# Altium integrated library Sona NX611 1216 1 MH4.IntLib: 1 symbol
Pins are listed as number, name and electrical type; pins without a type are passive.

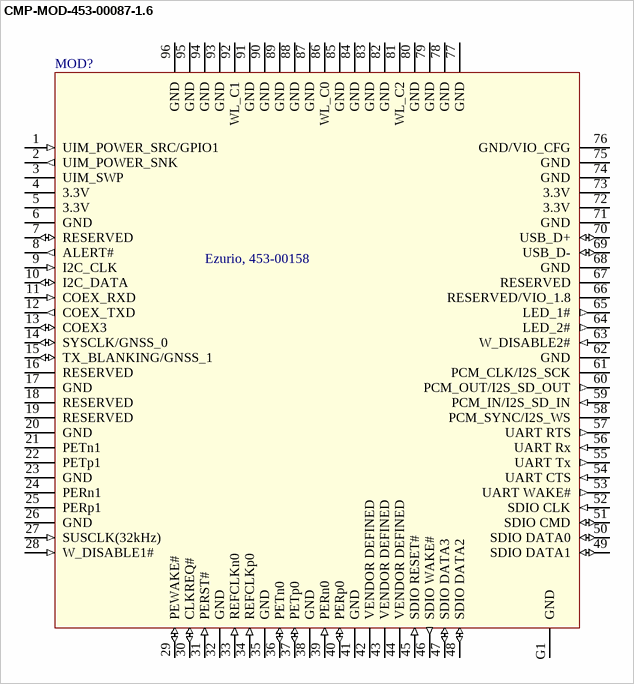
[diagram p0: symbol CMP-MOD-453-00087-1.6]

## CMP-MOD-453-00087-1.6
designator MOD?, comment Ezurio, 453-00158
MOD, Sona NX612 1216 1 MH4 Component side; Substitutes Allowed: NO
footprint Laird, M.2 1216 Module Component Side 1 MH4 (Laird, M2.1216 Module Component Side 1 MH4)
pins: 1 UIM_POWER_SRC/GPIO1 (in), 2 UIM_POWER_SNK (out), 3 UIM_SWP, 4 3.3V, 5 3.3V, 6 GND, 7 RESERVED (io), 8 ALERT# (out), 9 I2C_CLK (in), 10 I2C_DATA (io), 11 COEX_RXD (in), 12 COEX_TXD (out), 13 COEX3 (io), 14 SYSCLK/GNSS_0 (io), 15 TX_BLANKING/GNSS_1 (io), 16 RESERVED, 17 GND, 18 RESERVED, 19 RESERVED, 20 GND, 21 PETn1, 22 PETp1, 23 GND, 24 PERn1, 25 PERp1, 26 GND, 27 SUSCLK(32kHz) (in), 28 W_DISABLE1# (in), 29 PEWAKE# (io), 30 CLKREQ# (io), 31 PERST# (in), 32 GND, 33 REFCLKn0 (in), 34 REFCLKp0 (in), 35 GND, 36 PETn0 (io), 37 PETp0 (io), 38 GND, 39 PERn0 (in), 40 PERp0 (io), 41 GND, 42 VENDOR DEFINED, 43 VENDOR DEFINED, 44 VENDOR DEFINED, 45 SDIO RESET# (in), 46 SDIO WAKE# (out), 47 SDIO DATA3 (io), 48 SDIO DATA2 (io), 49 SDIO DATA1 (io), 50 SDIO DATA0 (io), 51 SDIO CMD (io), 52 SDIO CLK (in), 53 UART WAKE# (out), 54 UART CTS (in), 55 UART Tx (out), 56 UART Rx (in), 57 UART RTS (out), 58 PCM_SYNC/I2S_WS, 59 PCM_IN/I2S_SD_IN (in), 60 PCM_OUT/I2S_SD_OUT (out), 61 PCM_CLK/I2S_SCK, 62 GND, 63 W_DISABLE2# (in), 64 LED_2# (out), 65 LED_1# (out), 66 RESERVED/VIO_1.8, 67 RESERVED, 68 GND, 69 USB_D- (io), 70 USB_D+ (io), 71 GND, 72 3.3V, 73 3.3V, 74 GND, 75 GND, 76 GND/VIO_CFG, 77 GND, 78 GND, 79 GND, 80 GND, 81 WL_C2, 82 GND, 83 GND, 84 GND, 85 GND, 86 WL_C0, 87 GND, 88 GND, 89 GND, 90 GND, 91 GND, 92 WL_C1, 93 GND, 94 GND, 95 GND, 96 GND, G1 GND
